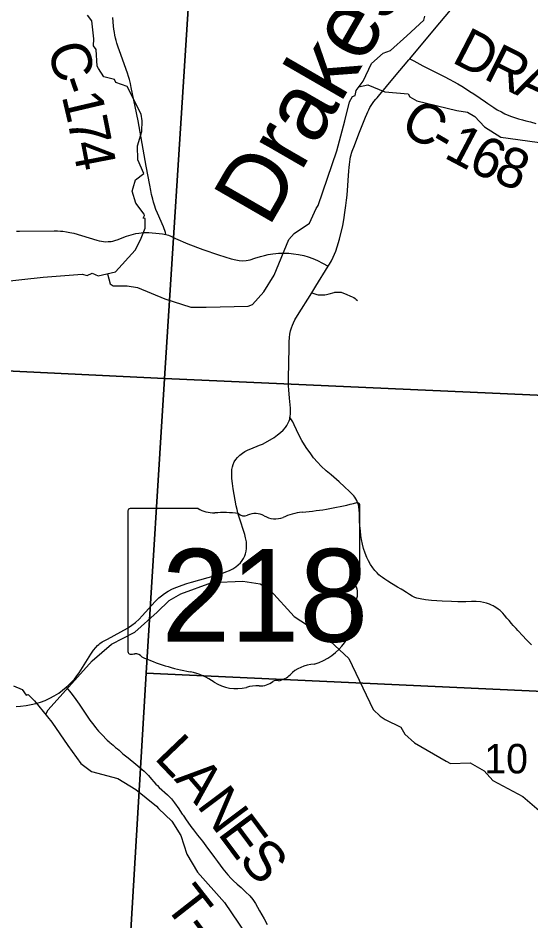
# Model space of a CAD drawing. Extents: x 0 to 34, y 0 to 22.
# Drawn here: x 4.884 to 5.613, y 16.555 to 17.839 of the extents above; entities that cross this region are included whole.
import ezdxf

# ---------------------------------------------------------------- set-up
doc = ezdxf.new("R2010")
doc.units = 0
for name, color, linetype in [('GM_X_County_Road', 7, 'Continuous'), ('GM_X_County_Road_Text', 7, 'Continuous'), ('GM_X_Minor_River', 7, 'Continuous'), ('GM_X_Minor_River_Text', 7, 'Continuous'), ('GM_X_Section', 7, 'Continuous'), ('GM_X_Section_Text', 7, 'Continuous'), ('GM_X_State_Location', 7, 'Continuous'), ('GM_X_State_Route', 7, 'Continuous'), ('GM_X_State_Shield', 7, 'Continuous'), ('GM_X_Township_Road', 7, 'Continuous'), ('GM_X_Township_Road_Text', 7, 'Continuous')]:
    doc.layers.add(name, color=color, linetype=linetype)

msp = doc.modelspace()

# ---------------------------------------------------------------- linework, layer by layer
at = {"layer": 'GM_X_County_Road'}
for points in [[(5.0942, 17.5312), (5.0935, 17.5341), (5.0927, 17.5369), (5.0918, 17.5392), (5.0907, 17.5419), (5.0822, 17.5614), (5.0801, 17.5667), (5.078, 17.573), (5.0768, 17.5769), (5.0755, 17.5813), (5.074, 17.5879), (5.0729, 17.5939), (5.0716, 17.6013), (5.0663, 17.6282), (5.0546, 17.6927), (5.0505, 17.7129), (5.045, 17.74), (5.0439, 17.746), (5.0425, 17.7517), (5.0413, 17.7559), (5.0398, 17.7606), (5.0281, 17.7922), (5.0262, 17.7975), (5.0244, 17.8032), (5.0233, 17.8071), (5.0225, 17.8104), (5.0217, 17.8144), (5.021, 17.8185), (5.0203, 17.823), (5.0197, 17.8275), (5.0191, 17.8336), (5.0188, 17.8394)], [(5.4411, 17.781), (5.4467, 17.7779), (5.4599, 17.7707), (5.4748, 17.7631), (5.4899, 17.7557), (5.4981, 17.7515), (5.5035, 17.7485), (5.5094, 17.7452), (5.5151, 17.7418), (5.5217, 17.7377), (5.5266, 17.7346), (5.532, 17.7312), (5.5411, 17.7251), (5.5488, 17.7197), (5.5522, 17.7174), (5.5606, 17.7116), (5.5656, 17.7085), (5.5715, 17.7053), (5.5764, 17.7029), (5.5844, 17.6995), (5.5885, 17.698), (5.5956, 17.6958), (5.6015, 17.6941), (5.6063, 17.6928), (5.6128, 17.6911), (5.6204, 17.6889)], [(4.882, 17.536), (4.8861, 17.5361), (4.9355, 17.5364), (4.9403, 17.5363), (4.9443, 17.5361), (4.9479, 17.5359), (4.9529, 17.5351), (4.9578, 17.5342), (4.9631, 17.5329), (4.9962, 17.5229), (4.9992, 17.5222), (5.0025, 17.5216), (5.0054, 17.5212), (5.0087, 17.5209), (5.0121, 17.521), (5.0162, 17.5214), (5.019, 17.5219), (5.0218, 17.5227), (5.0266, 17.5243), (5.032, 17.5265), (5.038, 17.5287), (5.0447, 17.5308), (5.0515, 17.5325), (5.0558, 17.5333), (5.0591, 17.5337), (5.0623, 17.5339), (5.0656, 17.5339), (5.0701, 17.5338), (5.0749, 17.5335), (5.0798, 17.5332), (5.0845, 17.5327), (5.0896, 17.5321), (5.0942, 17.5312), (5.0979, 17.53), (5.1013, 17.5287), (5.1043, 17.5274), (5.1081, 17.5257), (5.1255, 17.5177), (5.1466, 17.5097), (5.1691, 17.5021), (5.1873, 17.4966), (5.1935, 17.495), (5.1986, 17.4941), (5.2038, 17.4938), (5.2086, 17.494), (5.2143, 17.4952), (5.2209, 17.4973), (5.2289, 17.5), (5.2344, 17.5015), (5.2397, 17.5027), (5.243, 17.5033), (5.2462, 17.5038), (5.2507, 17.5043), (5.2543, 17.5046), (5.2582, 17.5047), (5.2622, 17.5047), (5.2689, 17.5045), (5.2757, 17.5039), (5.283, 17.5028), (5.2902, 17.5012), (5.2967, 17.4993), (5.3031, 17.497), (5.3099, 17.4941), (5.317, 17.4904), (5.3252, 17.4861)], [(5.614, 16.9477), (5.6106, 16.9516), (5.6067, 16.9557), (5.6019, 16.9607), (5.5949, 16.9681), (5.5923, 16.971), (5.5883, 16.9754), (5.5857, 16.9784), (5.5823, 16.9824), (5.5793, 16.986), (5.576, 16.9901), (5.5735, 16.9929), (5.5696, 16.9966), (5.5669, 16.9988), (5.565, 17.0001), (5.5613, 17.0025), (5.5597, 17.0034), (5.5574, 17.0045), (5.5547, 17.0056), (5.5501, 17.0072), (5.5459, 17.0083), (5.5417, 17.0091), (5.5356, 17.0096), (5.5289, 17.0095), (5.521, 17.0091), (5.5174, 17.009), (5.5136, 17.0091), (5.5093, 17.009), (5.5002, 17.0093), (5.4873, 17.0098), (5.472, 17.0109), (5.4634, 17.0118), (5.456, 17.0131), (5.4512, 17.0143), (5.4482, 17.0154), (5.4447, 17.0171), (5.4409, 17.0193), (5.4364, 17.0225), (5.4312, 17.0258), (5.429, 17.027), (5.4237, 17.0301), (5.4152, 17.0351), (5.4099, 17.0383), (5.4056, 17.0413), (5.4022, 17.0436), (5.3996, 17.0456), (5.3973, 17.0475), (5.3946, 17.0501), (5.3916, 17.0534), (5.3885, 17.0573), (5.3853, 17.062), (5.3822, 17.0675), (5.38, 17.072), (5.3775, 17.0784), (5.3753, 17.0849), (5.3738, 17.091), (5.3725, 17.0978), (5.3716, 17.1033), (5.3709, 17.1095), (5.3702, 17.1176), (5.3698, 17.1238), (5.3695, 17.13), (5.3694, 17.1344), (5.3692, 17.1399), (5.3687, 17.1439), (5.368, 17.147), (5.3668, 17.1504), (5.3658, 17.153), (5.3644, 17.1555), (5.363, 17.1577), (5.3614, 17.1598), (5.3591, 17.1623), (5.3553, 17.1661), (5.3484, 17.1725), (5.3407, 17.1795), (5.3294, 17.1894), (5.3224, 17.1954), (5.3149, 17.202), (5.3098, 17.2075), (5.3044, 17.2138), (5.2992, 17.2209), (5.2947, 17.2272), (5.2913, 17.2324), (5.2876, 17.2385), (5.2838, 17.2456), (5.2799, 17.2536), (5.2767, 17.2608), (5.2748, 17.2648), (5.2729, 17.2679), (5.2707, 17.2711)]]:
    msp.add_lwpolyline(points, dxfattribs=at)
at = {"layer": 'GM_X_Minor_River'}
for points in [[(4.8591, 17.4641), (4.9196, 17.4703), (4.9751, 17.4746), (4.9823, 17.4731), (4.9895, 17.4761), (4.9978, 17.4724), (5.0228, 17.4781), (5.0507, 17.509), (5.0579, 17.5234), (5.0647, 17.5402), (5.065, 17.5538), (5.062, 17.5546), (5.0639, 17.558), (5.0635, 17.5599), (5.0514, 17.5759), (5.0465, 17.5929), (5.0476, 17.5975), (5.051, 17.6089), (5.0631, 17.6177), (5.0544, 17.6371), (5.054, 17.6572), (5.06, 17.6774), (5.0607, 17.6926), (5.0592, 17.7024), (5.0391, 17.7415), (5.0229, 17.7472), (5.021, 17.7514), (5.0062, 17.7555), (4.9983, 17.7673), (4.9964, 17.7703), (4.9953, 17.7943), (4.9911, 17.7992), (4.9918, 17.8095), (4.9888, 17.8349), (4.9827, 17.8429)], [(5.0112, 17.4755), (5.0148, 17.461), (5.0194, 17.4583), (5.039, 17.458), (5.0538, 17.4558), (5.0927, 17.4399), (5.1298, 17.4278), (5.1517, 17.4279), (5.2111, 17.4295), (5.2175, 17.4318), (5.2333, 17.4497), (5.2481, 17.4733), (5.2692, 17.5239), (5.2767, 17.5327), (5.2983, 17.5472), (5.3081, 17.5681), (5.3107, 17.5723), (5.3375, 17.6499), (5.3488, 17.6928), (5.3556, 17.7198), (5.3597, 17.7275), (5.3635, 17.7286), (5.365, 17.7358), (5.3748, 17.7492), (5.3865, 17.7743), (5.4031, 17.7887), (5.4137, 17.7929), (5.4371, 17.8135), (5.4613, 17.836), (5.4624, 17.8417)], [(5.3683, 17.741), (5.3814, 17.7438), (5.4057, 17.7339), (5.4389, 17.7313), (5.4414, 17.7267), (5.451, 17.7211), (5.5079, 17.7075)], [(5.5079, 17.7075), (5.5231, 17.7051), (5.5335, 17.6987), (5.5474, 17.6842), (5.5704, 17.6694), (5.6359, 17.6605)], [(4.9233, 16.8495), (4.9269, 16.8554), (4.9895, 16.9252), (5.0167, 16.949), (5.0501, 16.9661), (5.0816, 16.9944), (5.0987, 17.0109), (5.1156, 17.0202), (5.1596, 17.0367), (5.2035, 17.0383), (5.2283, 17.0345), (5.2428, 17.0253), (5.2765, 16.9882), (5.3213, 16.9594), (5.3544, 16.9283), (5.3889, 16.8558), (5.3988, 16.8464), (5.4062, 16.842), (5.4282, 16.831), (5.4339, 16.821), (5.4479, 16.8088), (5.4929, 16.7825)], [(4.8774, 16.8898), (4.8899, 16.8846), (4.8955, 16.8766), (4.8982, 16.8774), (4.9076, 16.8683), (4.9322, 16.8379), (4.9549, 16.8049), (4.9735, 16.7791), (4.9826, 16.7723), (4.9886, 16.7681), (5.0257, 16.7579), (5.0514, 16.7424), (5.0809, 16.7185), (5.0836, 16.7151), (5.1029, 16.6973), (5.1157, 16.6768), (5.1241, 16.6502), (5.1392, 16.6248), (5.1778, 16.5816), (5.2172, 16.5231)], [(5.4929, 16.7825), (5.4992, 16.7794), (5.5268, 16.7801), (5.5469, 16.7688), (5.5593, 16.7551), (5.6017, 16.7325), (5.6385, 16.7009), (5.6458, 16.6904), (5.6602, 16.6551), (5.663, 16.6489), (5.7122, 16.623), (5.7619, 16.6191), (5.7887, 16.6153), (5.8486, 16.5985), (5.8698, 16.5975), (5.8909, 16.5949), (5.9546, 16.5667), (5.9803, 16.5643), (6.0166, 16.5772), (6.0605, 16.5811), (6.0817, 16.5949), (6.0879, 16.5989), (6.1258, 16.6261)]]:
    msp.add_lwpolyline(points, dxfattribs=at)
at = {"layer": 'GM_X_Section'}
for points in [[(4.1036, 18.4009), (5.1578, 18.3486), (5.0921, 17.3266), (4.0444, 17.3771)], [(5.1578, 18.3486), (6.1942, 18.2962), (6.1312, 17.2799), (5.0921, 17.3266)], [(4.0444, 17.3771), (5.0921, 17.3266), (5.0662, 16.9077), (5.041, 16.4863), (5.0334, 16.328), (4.4335, 16.3564), (3.9862, 16.3827), (3.9864, 16.3863), (3.9959, 16.5649), (4.0188, 16.9784)], [(5.0921, 17.3266), (6.1312, 17.2799), (6.1041, 16.8596), (5.0662, 16.9077)], [(6.1041, 16.8596), (6.0768, 16.4347), (5.041, 16.4863), (5.0662, 16.9077)]]:
    msp.add_lwpolyline(points, close=True, dxfattribs=at)
at = {"layer": 'GM_X_State_Route'}
msp.add_lwpolyline([(4.8811, 16.8605), (4.8873, 16.8609), (4.8954, 16.8617), (4.9028, 16.8629), (4.9095, 16.8645), (4.9161, 16.8665), (4.9226, 16.8689), (4.9294, 16.872), (4.9355, 16.8753), (4.9418, 16.8794), (4.9473, 16.8835), (4.9524, 16.8877), (4.9559, 16.8908), (4.96, 16.8948), (4.9642, 16.8993), (4.9678, 16.9037), (4.9711, 16.9082), (4.9876, 16.9346), (4.9913, 16.9402), (4.9944, 16.944), (4.9971, 16.9471), (4.9987, 16.9485), (5.0004, 16.9498), (5.0037, 16.9521), (5.0075, 16.9543), (5.0111, 16.9562), (5.0395, 16.9715), (5.0457, 16.9757), (5.0512, 16.9799), (5.0563, 16.9845), (5.0606, 16.9891), (5.0788, 17.0095), (5.0841, 17.0146), (5.0878, 17.0178), (5.0922, 17.0211), (5.0974, 17.0243), (5.1035, 17.0274), (5.1097, 17.0301), (5.1172, 17.0329), (5.1238, 17.035), (5.1308, 17.0371), (5.1661, 17.0469), (5.174, 17.0494), (5.1796, 17.0515), (5.1849, 17.0537), (5.1895, 17.0561), (5.1937, 17.0587), (5.1971, 17.0616), (5.2003, 17.0647), (5.2027, 17.0676), (5.2048, 17.0708), (5.2065, 17.0743), (5.2077, 17.0773), (5.2086, 17.081), (5.2091, 17.0848), (5.2091, 17.0892), (5.2087, 17.0942), (5.2077, 17.0998), (5.2064, 17.1047), (5.1984, 17.1295), (5.1966, 17.1352), (5.1954, 17.1402), (5.1942, 17.1456), (5.1899, 17.1698), (5.1889, 17.1774), (5.1882, 17.1845), (5.1879, 17.1895), (5.1878, 17.1936), (5.188, 17.1971), (5.1888, 17.2009), (5.1898, 17.2044), (5.1915, 17.2081), (5.1938, 17.2114), (5.1963, 17.2144), (5.1996, 17.2177), (5.2034, 17.2205), (5.2067, 17.2227), (5.2111, 17.225), (5.2151, 17.2267), (5.2276, 17.2316), (5.2318, 17.2332), (5.2358, 17.2353), (5.2481, 17.2427), (5.2532, 17.2463), (5.2571, 17.2495), (5.261, 17.2531), (5.2642, 17.2567), (5.2663, 17.2597), (5.2682, 17.2633), (5.2694, 17.2661), (5.2703, 17.2689), (5.2707, 17.2711), (5.271, 17.2724), (5.2714, 17.2764), (5.2715, 17.2807), (5.2713, 17.2845), (5.2701, 17.2985), (5.269, 17.3105), (5.2687, 17.3163), (5.2686, 17.3214), (5.2686, 17.3268), (5.2695, 17.3703), (5.2697, 17.3784), (5.2702, 17.3846), (5.2707, 17.3894), (5.2716, 17.3942), (5.2728, 17.3985), (5.2741, 17.4023), (5.2756, 17.4058), (5.2778, 17.41), (5.2814, 17.416), (5.3017, 17.4484), (5.3075, 17.4578), (5.3252, 17.4861), (5.3269, 17.4888), (5.3297, 17.4939), (5.3323, 17.499), (5.3341, 17.5032), (5.3357, 17.5074), (5.3377, 17.5135), (5.341, 17.5247), (5.3457, 17.5441), (5.3473, 17.5521), (5.3494, 17.5657), (5.3503, 17.5724), (5.3512, 17.5798), (5.3519, 17.5872), (5.3546, 17.6218), (5.3549, 17.6266), (5.3553, 17.6309), (5.3557, 17.6344), (5.3563, 17.6382), (5.357, 17.6416), (5.3577, 17.6443), (5.3584, 17.6469), (5.3593, 17.6495), (5.3602, 17.6519), (5.3614, 17.6552), (5.3698, 17.6767), (5.3782, 17.698), (5.3799, 17.7021), (5.3814, 17.7056), (5.3828, 17.7086), (5.3845, 17.7117), (5.3861, 17.7147), (5.3879, 17.7175), (5.3899, 17.7201), (5.3926, 17.7235), (5.3945, 17.7256), (5.3964, 17.7279), (5.4195, 17.7552), (5.4399, 17.7796), (5.4411, 17.781), (5.4763, 17.823), (5.4989, 17.85)], dxfattribs=at)
at = {"layer": 'GM_X_State_Shield'}
for p, q in [((5.3699, 17.0421), (5.3699, 17.1468)), ((5.0403, 17.1384), (5.0403, 16.9383)), ((5.14, 17.1418), (5.0435, 17.1418)), ((5.3698, 17.0421), (5.3699, 17.0421))]:
    msp.add_line(p, q, dxfattribs=at)
for centre, major_axis, start_param, end_param in [((5.2525, 17.4147), (0.3495, 0), 4.814394, 5.042369), ((5.3662, 17.1472), (0.00367, 0), 6.141152, 7.989035), ((5.0441, 17.1388), (0.00382, 0), 1.712693, 3.28349), ((5.163, 17.1651), (0.037, 0), 4.042523, 4.731795), ((5.1753, 17.0295), (0.133, 0), 1.404758, 1.657858), ((5.2055, 17.1399), (0.0107, 0), 3.836095, 5.185415), ((5.2212, 17.1167), (0.0222, 0), 0.950623, 2.079405), ((5.297, 17.0807), (0.0703, 0), 1.699011, 2.107814), ((5.2498, 17.1485), (0.0267, 0), 4.081561, 5.145723), ((5.369, 17.0344), (0.00568, 0), 1.883978, 3.671073), ((5.3329, 17.0212), (0.0341, 0), 5.934695, 6.695948), ((5.3659, 17.0417), (0.00393, 0), 5.05454, 6.418171), ((5.383, 16.9983), (0.0248, 0), 2.387724, 3.262537), ((5.272, 16.985), (0.0874, 0), 5.101752, 6.440018), ((5.0441, 16.9378), (0.00385, 0), 3.00124, 4.508301), ((5.0447, 16.9583), (0.0294, 0), 4.665946, 4.897461), ((5.0507, 16.9267), (0.0106, 0), 0.519207, 1.627899), ((5.1845, 17.1065), (0.2524, 0), 4.195997, 4.488961), ((5.3089, 16.8821), (0.0479, 0), 1.647645, 2.488434), ((5.1093, 16.8484), (0.079, 0), 0.823519, 1.323587), ((5.2482, 16.9189), (0.0282, 0), 4.937069, 5.64225), ((5.1947, 16.9257), (0.0501, 0), 4.026481, 4.996735), ((5.2236, 16.8566), (0.0412, 0), 1.495662, 1.94098), ((5.2273, 16.9108), (0.0267, 0), 4.691044, 5.507374), ((5.2514, 16.8914), (0.00752, 0), 1.147584, 2.315152)]:
    msp.add_ellipse(centre, major_axis=major_axis, ratio=0.8, start_param=start_param, end_param=end_param, dxfattribs=at)
at = {"layer": 'GM_X_Township_Road'}
for points in [[(5.3017, 17.4484), (5.3046, 17.4474), (5.3074, 17.4464), (5.3091, 17.4458), (5.311, 17.4455), (5.3132, 17.4452), (5.3154, 17.4452), (5.3177, 17.4453), (5.3204, 17.4456), (5.3226, 17.4459), (5.3246, 17.4464), (5.3263, 17.4468), (5.3336, 17.4488), (5.3347, 17.4491), (5.3359, 17.4492), (5.3372, 17.4494), (5.3384, 17.4494), (5.3397, 17.4494), (5.341, 17.4493), (5.3422, 17.4492), (5.3434, 17.449), (5.3447, 17.4487), (5.3458, 17.4483), (5.3469, 17.4479), (5.3482, 17.4474), (5.3592, 17.4426), (5.3614, 17.4415), (5.3632, 17.4403), (5.365, 17.4389), (5.3667, 17.4373)], [(4.9524, 16.8877), (4.9571, 16.8819), (4.9611, 16.8771), (4.9663, 16.8701), (4.9708, 16.8634), (4.9802, 16.8495), (4.9863, 16.8409), (4.99, 16.836), (4.9945, 16.8301), (4.996, 16.8282), (4.9984, 16.8253), (5.0031, 16.8204), (5.0109, 16.8126), (5.0136, 16.81), (5.0145, 16.8092), (5.0168, 16.8072), (5.0191, 16.8052), (5.0228, 16.8019), (5.0252, 16.7999), (5.0276, 16.798), (5.0332, 16.7932), (5.0404, 16.7874), (5.0515, 16.7785), (5.0577, 16.7732), (5.0632, 16.7682), (5.0694, 16.762), (5.0739, 16.7569), (5.0772, 16.7531), (5.0801, 16.7499), (5.0824, 16.7478), (5.0849, 16.7452), (5.0963, 16.7346), (5.102, 16.7288), (5.1065, 16.7233), (5.1126, 16.7149), (5.1143, 16.7123), (5.1176, 16.7071), (5.1187, 16.7056), (5.1206, 16.7031), (5.1223, 16.7006), (5.1298, 16.6899), (5.1337, 16.6849), (5.1393, 16.6775), (5.1462, 16.6689), (5.1536, 16.6589), (5.158, 16.6529), (5.1635, 16.6454), (5.1676, 16.6399), (5.1754, 16.6295), (5.1825, 16.6209), (5.1871, 16.616), (5.1901, 16.6128), (5.1956, 16.6078), (5.2011, 16.6029), (5.2076, 16.597), (5.2134, 16.5913), (5.2178, 16.586), (5.2217, 16.5803), (5.2276, 16.57), (5.2338, 16.5585), (5.2383, 16.5503)]]:
    msp.add_lwpolyline(points, dxfattribs=at)

# ---------------------------------------------------------------- texts
at = {"layer": 'GM_X_County_Road_Text'}
for s, rotation, p in [('D', 332.6448, (5.4991, 17.7768)), ('C', 285.9744, (4.9251, 17.7965)), ('R', 333.3021, (5.5441, 17.7535)), ('A', 335.2103, (5.5877, 17.7317)), ('-', 288.6765, (4.9389, 17.7488)), ('1', 283.2417, (4.9459, 17.7281)), ('C', 328.6259, (5.4246, 17.6793)), ('7', 281.139, (4.9538, 17.6945)), ('-', 329.6337, (5.4654, 17.6544)), ('1', 332.1583, (5.4879, 17.6413)), ('4', 280.916, (4.9606, 17.6603)), ('6', 335.1745, (5.5218, 17.6235)), ('8', 339.4981, (5.5579, 17.607))]:
    msp.add_text(s, height=0.0568, rotation=rotation, dxfattribs=at).set_placement(p)
at = {"layer": 'GM_X_Minor_River_Text'}
msp.add_text('Drakes', height=0.09469, rotation=59.9948, dxfattribs=at).set_placement((5.2403, 17.5398))
at = {"layer": 'GM_X_Section_Text'}
msp.add_text('10', height=0.04186, rotation=0, dxfattribs=at).set_placement((5.547, 16.7652))
at = {"layer": 'GM_X_State_Location'}
for s in ['s', 'r']:
    msp.add_text(s, height=0.000189, dxfattribs=at).set_placement((5.2014, 17.025))
msp.add_text('218', height=0.000189, rotation=0, dxfattribs=at).set_placement((5.1345, 17.0113))
at = {"layer": 'GM_X_State_Shield'}
msp.add_text('218', height=0.13184, dxfattribs=at).set_placement((5.0879, 16.9524))
at = {"layer": 'GM_X_Township_Road_Text'}
for s, rotation, p in [('L', 313.7196, (5.0762, 16.7867)), ('A', 310.7937, (5.1051, 16.7566)), ('N', 306.8054, (5.1371, 16.7195)), ('E', 306.7165, (5.167, 16.6795)), ('S', 312.0447, (5.1961, 16.641)), ('T', 308.0554, (5.0903, 16.5783)), ('-', 306.8199, (5.1163, 16.5451))]:
    msp.add_text(s, height=0.0568, rotation=rotation, dxfattribs=at).set_placement(p)

doc.saveas('drawing.dxf')
